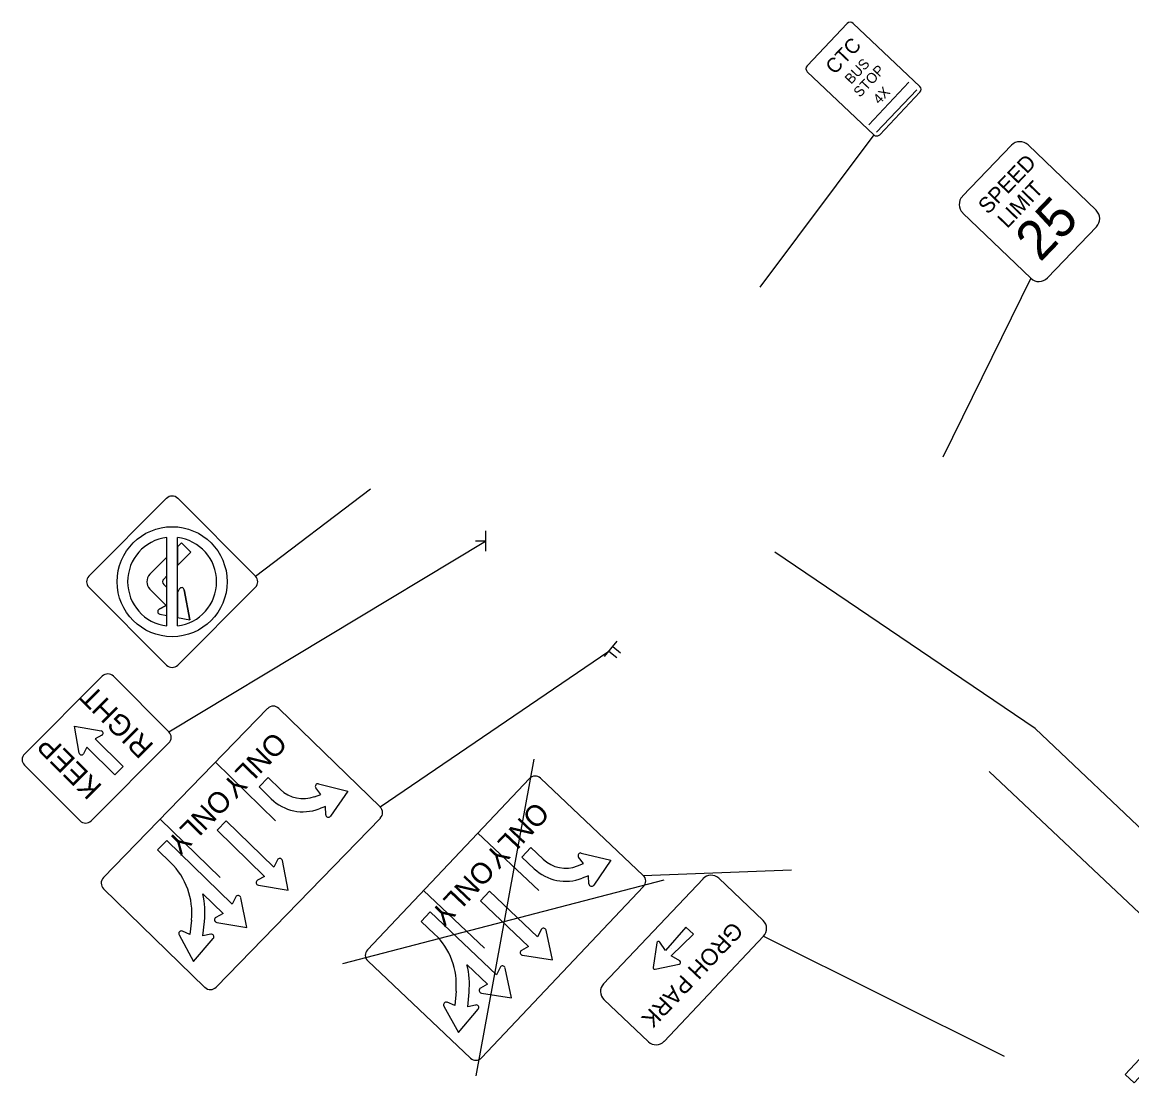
# Model space of a CAD drawing. Extents: x 1481212 to 1485683, y 378085 to 388655.
# Drawn here: x 1481212.4 to 1481389, y 378251 to 378419.7 of the extents above; entities that cross this region are included whole.
import ezdxf

# ---------------------------------------------------------------- set-up
doc = ezdxf.new("R2010")
doc.units = 0
for name, color, linetype in [('RW_X_CL_100_Bearings', 7, 'Continuous'), ('RW_X_CL_100_Curve_Data', 7, 'Continuous'), ('RW_X_CL_500_Distances', 7, 'Continuous'), ('RW_X_CL_500_Stations', 7, 'Continuous'), ('SN_P_Signs', 7, 'Continuous')]:
    doc.layers.add(name, color=color, linetype=linetype)

msp = doc.modelspace()

# ---------------------------------------------------------------- linework, layer by layer
at = {"layer": 'RW_X_CL_100_Bearings'}
msp.add_line((1481401.7, 378267.11), (1481366.27, 378300.56), dxfattribs=at)
at = {"layer": 'RW_X_CL_100_Curve_Data'}
for p, q in [((1481353.49, 378410.16), (1481347.1, 378403.42)), ((1481354.73, 378408.99), (1481348.34, 378402.25)), ((1481347.92, 378401.8), (1481329.79, 378377.6)), ((1481372.89, 378378.99), (1481358.91, 378350.54)), ((1481249.52, 378331.62), (1481267.84, 378345.51)), ((1481235.43, 378323.71), (1481235.43, 378337.77)), ((1481235.75, 378306.87), (1481286.14, 378337.21)), ((1481286.14, 378337.21), (1481284.54, 378337.21)), ((1481286.14, 378338.81), (1481286.14, 378335.61)), ((1481237.1, 378336.29), (1481237.74, 378336.93)), ((1481237.74, 378336.93), (1481237.1, 378336.29)), ((1481237.1, 378336.29), (1481237.1, 378334.54)), ((1481237.1, 378333.34), (1481239.21, 378335.45)), ((1481237.1, 378333.34), (1481239.21, 378335.45)), ((1481237.74, 378336.93), (1481239.21, 378335.45)), ((1481239.21, 378335.45), (1481237.74, 378336.93)), ((1481232.73, 378331.92), (1481235.43, 378334.62)), ((1481235.43, 378334.62), (1481232.73, 378331.92)), ((1481235.43, 378334.54), (1481235.43, 378334.62)), ((1481235.43, 378331.67), (1481235.43, 378334.54)), ((1481237.1, 378334.54), (1481237.1, 378333.34)), ((1481234.92, 378331.16), (1481235.43, 378331.67)), ((1481234.92, 378331.16), (1481235.43, 378331.67)), ((1481234.92, 378330.32), (1481235.43, 378329.81)), ((1481235.43, 378329.81), (1481234.92, 378330.32)), ((1481232.73, 378329.56), (1481235.33, 378326.96)), ((1481232.73, 378329.56), (1481235.33, 378326.96)), ((1481235.43, 378325.37), (1481235.43, 378329.81)), ((1481237.4, 378329.57), (1481237.1, 378329)), ((1481237.4, 378329.57), (1481237.1, 378329)), ((1481237.1, 378329), (1481237.1, 378325.06)), ((1481238.18, 378329.45), (1481239.06, 378324.7)), ((1481239.06, 378324.7), (1481238.18, 378329.45)), ((1481234.19, 378326.36), (1481235.33, 378326.96)), ((1481235.33, 378326.96), (1481234.19, 378326.36)), ((1481234.31, 378325.58), (1481235.43, 378325.37)), ((1481234.31, 378325.58), (1481235.43, 378325.37)), ((1481237.1, 378325.06), (1481239.06, 378324.7)), ((1481237.1, 378325.06), (1481239.06, 378324.7)), ((1481221.47, 378303.49), (1481220.72, 378307.75)), ((1481220.72, 378307.75), (1481224.98, 378307.01)), ((1481225.09, 378306.32), (1481224.03, 378305.77)), ((1481224.03, 378305.77), (1481228.46, 378301.34)), ((1481222.7, 378304.45), (1481222.15, 378303.39)), ((1481227.13, 378300.02), (1481222.7, 378304.45)), ((1481228.46, 378301.34), (1481227.13, 378300.02)), ((1481294.6, 378281.61), (1481284.91, 378290.77)), ((1481291.91, 378286.95), (1481293.34, 378288.46)), ((1481293.34, 378288.46), (1481295.3, 378286.6)), ((1481293.87, 378285.09), (1481291.91, 378286.95)), ((1481301.74, 378285.91), (1481300.94, 378286.92)), ((1481301.36, 378287.58), (1481306.07, 378286.46)), ((1481306.07, 378286.46), (1481303.34, 378282.47)), ((1481300.76, 378285.53), (1481301.74, 378285.91)), ((1481311.22, 378284.03), (1481334.82, 378284.94)), ((1481302.49, 378283.97), (1481301.51, 378283.59)), ((1481302.58, 378282.68), (1481302.49, 378283.97)), ((1481285.94, 378272.45), (1481276.25, 378281.61)), ((1481286.75, 378281.5), (1481285.32, 378279.99)), ((1481294.42, 378274.25), (1481286.75, 378281.5)), ((1481285.32, 378279.99), (1481292.99, 378272.73)), ((1481277.34, 378278.22), (1481275.91, 378276.7)), ((1481287.89, 378268.24), (1481277.34, 378278.22)), ((1481275.91, 378276.7), (1481278.03, 378274.7)), ((1481294.99, 378275.4), (1481294.42, 378274.25)), ((1481317.99, 378275.8), (1481314.76, 378272.09)), ((1481319.2, 378274.66), (1481317.99, 378275.8)), ((1481296.78, 378270.58), (1481295.77, 378275.31)), ((1481315.67, 378271.23), (1481319.2, 378274.66)), ((1481330.38, 378274.38), (1481368.65, 378255.29)), ((1481292.99, 378272.73), (1481291.87, 378272.1)), ((1481313.39, 378273.3), (1481312.78, 378269.4)), ((1481314.76, 378272.09), (1481313.88, 378273.4)), ((1481315.71, 378272.4), (1481315.71, 378272.4)), ((1481292.01, 378271.33), (1481296.78, 378270.58)), ((1481317.03, 378270.43), (1481315.67, 378271.23)), ((1481283.18, 378269.82), (1481286.46, 378266.73)), ((1481288.45, 378269.4), (1481287.89, 378268.24)), ((1481290.25, 378264.58), (1481289.23, 378269.3)), ((1481313.1, 378269.1), (1481316.95, 378269.93)), ((1481286.46, 378266.73), (1481285.33, 378266.1)), ((1481281.43, 378265.63), (1481281.22, 378263.35)), ((1481283.29, 378263.15), (1481283.51, 378265.44)), ((1481285.47, 378265.32), (1481290.25, 378264.58)), ((1481279.5, 378263.26), (1481281.85, 378259.04)), ((1481281.22, 378263.35), (1481280.03, 378263.85)), ((1481284.55, 378263.42), (1481283.29, 378263.15)), ((1481281.85, 378259.04), (1481284.96, 378262.74))]:
    msp.add_line(p, q, dxfattribs=at)
for points in [[(1481337.3, 378412.77), (1481343.68, 378419.51)], [(1481344.62, 378419.54), (1481355.22, 378409.51)], [(1481347.92, 378401.8), (1481337.32, 378411.83)], [(1481355.24, 378408.57), (1481348.86, 378401.83)], [(1481369.8, 378400.15), (1481362.01, 378392.03)], [(1481383.27, 378389.82), (1481372.45, 378400.2)], [(1481362.07, 378389.37), (1481372.89, 378378.99)], [(1481375.54, 378379.05), (1481383.33, 378387.17)], [(1481223, 378331.62), (1481235.38, 378344)], [(1481237.15, 378344), (1481249.52, 378331.62)], [(1481237.1, 378334.54), (1481237.1, 378337.77)], [(1481237.1, 378323.71), (1481237.1, 378331.67), (1481237.1, 378334.54)], [(1481235.38, 378317.48), (1481223, 378329.86)], [(1481237.1, 378329), (1481237.1, 378329)], [(1481249.52, 378329.86), (1481237.15, 378317.48)], [(1481212.77, 378303.33), (1481225.14, 378315.71)], [(1481226.91, 378315.71), (1481235.75, 378306.87)], [(1481235.75, 378305.1), (1481223.37, 378292.73)], [(1481221.61, 378292.73), (1481212.77, 378301.56)], [(1481293.1, 378299.44), (1481267.34, 378272.19)], [(1481311.22, 378284.03), (1481294.87, 378299.49)], [(1481320.73, 378283.5), (1481304.9, 378266.77)], [(1481330.31, 378276.88), (1481323.23, 378283.57)], [(1481285.5, 378255.01), (1481311.27, 378282.26)], [(1481314.56, 378257.64), (1481330.38, 378274.38)], [(1481267.39, 378270.42), (1481283.74, 378254.96)], [(1481304.97, 378264.27), (1481312.05, 378257.57)]]:
    msp.add_lwpolyline(points, dxfattribs=at)
msp.add_circle((1481236.26, 378330.74), 8.75, dxfattribs=at)
for centre, radius, start, end in [((1481344.16, 378419.06), 0.663, 46.5645, 136.5645), ((1481337.78, 378412.32), 0.663, 136.5645, 226.5645), ((1481354.76, 378409.03), 0.663, 316.5645, 46.5645), ((1481348.38, 378402.29), 0.663, 226.5645, 316.5645), ((1481371.15, 378398.85), 1.87, 46.2, 136.2), ((1481363.36, 378390.73), 1.87, 136.2, 226.2), ((1481381.98, 378388.47), 1.87, 316.2, 46.2), ((1481374.19, 378380.35), 1.87, 226.2, 316.2), ((1481236.26, 378343.11), 1.25, 45, 135), ((1481236.26, 378330.74), 7.08, 96.7563, 263.2437), ((1481236.26, 378330.74), 7.08, 276.7563, 83.2437), ((1481236.26, 378330.74), 7.08, 276.7563, 83.2437), ((1481233.91, 378330.74), 1.67, 135, 225), ((1481233.91, 378330.74), 1.67, 135, 225), ((1481223.89, 378330.74), 1.25, 135, 225), ((1481235.34, 378330.74), 0.6, 135, 225), ((1481235.34, 378330.74), 0.6, 135, 225), ((1481248.64, 378330.74), 1.25, 315, 45), ((1481237.77, 378329.38), 0.417, 10.4837, 152.3618), ((1481237.77, 378329.38), 0.417, 10.4837, 152.3618), ((1481234.38, 378325.99), 0.417, 117.6382, 259.5163), ((1481234.38, 378325.99), 0.417, 117.6382, 259.5163), ((1481226.03, 378314.82), 1.25, 45, 135), ((1481236.26, 378318.37), 1.25, 225, 315), ((1481224.92, 378306.65), 0.365, 297.3622, 80.0792), ((1481234.86, 378305.98), 1.25, 315, 45), ((1481213.65, 378302.45), 1.25, 135, 225), ((1481221.83, 378303.55), 0.365, 189.9208, 332.6378), ((1481294.01, 378298.58), 1.25, 46.6, 136.6), ((1481222.49, 378293.61), 1.25, 225, 315), ((1481298.88, 378290.39), 5.21, 226.6, 291.1173), ((1481301.27, 378287.18), 0.417, 76.601, 218.4791), ((1481298.88, 378290.39), 7.29, 226.6, 291.1173), ((1481302.99, 378282.71), 0.417, 183.7555, 325.6336), ((1481310.36, 378283.12), 1.25, 316.6, 46.6), ((1481322.01, 378282.29), 1.77, 46.6, 136.6), ((1481295.36, 378275.22), 0.417, 12.0837, 153.9618), ((1481329.09, 378275.59), 1.77, 316.6, 46.6), ((1481270.44, 378266.68), 11.04, 354.5857, 46.6), ((1481268.25, 378271.33), 1.25, 136.6, 226.6), ((1481292.07, 378271.74), 0.417, 119.2382, 261.1163), ((1481313.66, 378273.25), 0.27, 33.6238, 171.0971), ((1481316.89, 378270.19), 0.27, 282.1029, 59.5762), ((1481270.44, 378266.68), 13.12, 354.5857, 13.8745), ((1481288.83, 378269.22), 0.417, 12.0837, 153.9618), ((1481313.05, 378269.37), 0.27, 172.5064, 280.6936), ((1481306.19, 378265.56), 1.77, 136.6, 226.6), ((1481285.53, 378265.74), 0.417, 119.2382, 261.1163), ((1481279.87, 378263.46), 0.417, 67.2239, 209.102), ((1481284.64, 378263.01), 0.417, 320.0694, 101.9475), ((1481313.27, 378258.86), 1.77, 226.6, 316.6), ((1481284.59, 378255.87), 1.25, 226.6, 316.6)]:
    msp.add_arc(centre, radius, start, end, dxfattribs=at)
at = {"layer": 'RW_X_CL_500_Distances'}
for q in [(1481332.18, 378335.42), (1481408.46, 378274.35)]:
    msp.add_line((1481373.57, 378307.38), q, dxfattribs=at)
at = {"layer": 'RW_X_CL_500_Stations'}
msp.add_lwpolyline([(1481409.9, 378273.06), (1481408.49, 378274.38), (1481387.93, 378252.37), (1481389.34, 378251.05)], close=True, dxfattribs=at)
at = {"layer": 'SN_P_Signs'}
for p, q in [((1481305.05, 378318.83), (1481307.09, 378321.3)), ((1481269.36, 378294.91), (1481305.76, 378319.69)), ((1481305.76, 378319.69), (1481307, 378318.68)), ((1481306.07, 378320.06), (1481306.07, 378320.06)), ((1481306.07, 378320.06), (1481306.07, 378320.06)), ((1481306.38, 378320.43), (1481307.61, 378319.42)), ((1481252.71, 378292.72), (1481243.15, 378302.02)), ((1481284.63, 378252.18), (1481293.88, 378302.52)), ((1481250.09, 378298.1), (1481251.54, 378299.59)), ((1481251.54, 378299.59), (1481253.49, 378297.7)), ((1481259.56, 378298.6), (1481264.24, 378297.41)), ((1481252.03, 378296.21), (1481250.09, 378298.1)), ((1481258.93, 378296.55), (1481259.91, 378296.92)), ((1481259.91, 378296.92), (1481259.13, 378297.94)), ((1481264.24, 378297.41), (1481261.46, 378293.46)), ((1481260.64, 378294.97), (1481259.65, 378294.6)), ((1481260.7, 378293.68), (1481260.64, 378294.97)), ((1481243.92, 378283.69), (1481234.36, 378292.98)), ((1481244.86, 378292.72), (1481243.41, 378291.23)), ((1481252.43, 378285.36), (1481244.86, 378292.72)), ((1481235.4, 378289.57), (1481233.95, 378288.08)), ((1481245.81, 378279.45), (1481235.4, 378289.57)), ((1481243.41, 378291.23), (1481250.98, 378283.87)), ((1481233.95, 378288.08), (1481236.04, 378286.04)), ((1481253.01, 378286.51), (1481252.43, 378285.36)), ((1481254.74, 378281.66), (1481253.8, 378286.4)), ((1481250.98, 378283.87), (1481249.85, 378283.25)), ((1481249.98, 378282.48), (1481254.74, 378281.66)), ((1481263.43, 378270.03), (1481314.57, 378283.33)), ((1481241.13, 378281.1), (1481244.36, 378277.96)), ((1481246.39, 378280.6), (1481245.81, 378279.45)), ((1481248.12, 378275.75), (1481247.17, 378280.49)), ((1481244.36, 378277.96), (1481243.23, 378277.34)), ((1481239.32, 378276.93), (1481239.07, 378274.65)), ((1481241.14, 378274.42), (1481241.39, 378276.71)), ((1481243.36, 378276.56), (1481248.12, 378275.75)), ((1481237.36, 378274.59), (1481239.65, 378270.33)), ((1481239.07, 378274.65), (1481237.89, 378275.16)), ((1481239.65, 378270.33), (1481242.81, 378273.99)), ((1481242.41, 378274.67), (1481241.14, 378274.42))]:
    msp.add_line(p, q, dxfattribs=at)
for points in [[(1481251.46, 378310.57), (1481225.32, 378283.68)], [(1481269.36, 378294.91), (1481253.23, 378310.59)], [(1481243.24, 378266.25), (1481269.39, 378293.14)], [(1481225.35, 378281.92), (1481241.48, 378266.23)]]:
    msp.add_lwpolyline(points, dxfattribs=at)
for centre, radius, start, end in [((1481252.36, 378309.7), 1.25, 45.8014, 135.8014), ((1481259.46, 378298.19), 0.417, 75.8024, 217.6805), ((1481257.12, 378301.44), 5.21, 225.8014, 290.3187), ((1481257.12, 378301.44), 7.29, 225.8014, 290.3187), ((1481268.49, 378294.01), 1.25, 315.8014, 45.8014), ((1481261.12, 378293.7), 0.417, 182.9568, 324.8349), ((1481228.35, 378278.13), 11.04, 353.7871, 45.8014), ((1481253.39, 378286.32), 0.417, 11.2851, 153.1632), ((1481226.22, 378282.81), 1.25, 135.8014, 225.8014), ((1481250.05, 378282.89), 0.417, 118.4395, 260.3176), ((1481228.35, 378278.13), 13.12, 353.7871, 13.0758), ((1481246.77, 378280.41), 0.417, 11.2851, 153.1632), ((1481243.43, 378276.97), 0.417, 118.4395, 260.3176), ((1481237.73, 378274.78), 0.417, 66.4252, 208.3033), ((1481242.49, 378274.26), 0.417, 319.2708, 101.1489), ((1481242.35, 378267.13), 1.25, 225.8014, 315.8014)]:
    msp.add_arc(centre, radius, start, end, dxfattribs=at)

# ---------------------------------------------------------------- texts
at = {"layer": 'RW_X_CL_100_Curve_Data'}
for s, height, rotation, p in [('CTC', 2.321, 46.5645, (1481341.68, 378411.28)), ('BUS', 1.625, 46.5645, (1481344.3, 378409.75)), ('STOP', 1.625, 46.5645, (1481345.69, 378407.67)), ('4X', 1.625, 46.5645, (1481348.79, 378406.56)), ('SPEED', 2.5, 46.2, (1481366.07, 378389.04)), ('LIMIT', 2.5, 46.2, (1481369.14, 378386.82)), ('25', 6.25, 46.2, (1481374.38, 378381.45)), ('RIGHT', 3.333, 135, (1481233.49, 378304.71)), ('KEEP', 3.333, 135, (1481225.26, 378298.2)), ('ONLY', 3.333, 226.6, (1481294.13, 378295.97)), ('ONLY', 3.333, 226.6, (1481285.47, 378286.81)), ('GROH PARK', 2.657, 226.6, (1481325.42, 378276.86))]:
    msp.add_text(s, height=height, rotation=rotation, dxfattribs=at).set_placement(p)
at = {"layer": 'SN_P_Signs'}
for p in [(1481252.44, 378307.09), (1481243.65, 378298.05)]:
    msp.add_text('ONLY', height=3.333, rotation=225.8014, dxfattribs=at).set_placement(p)

doc.saveas('drawing.dxf')
